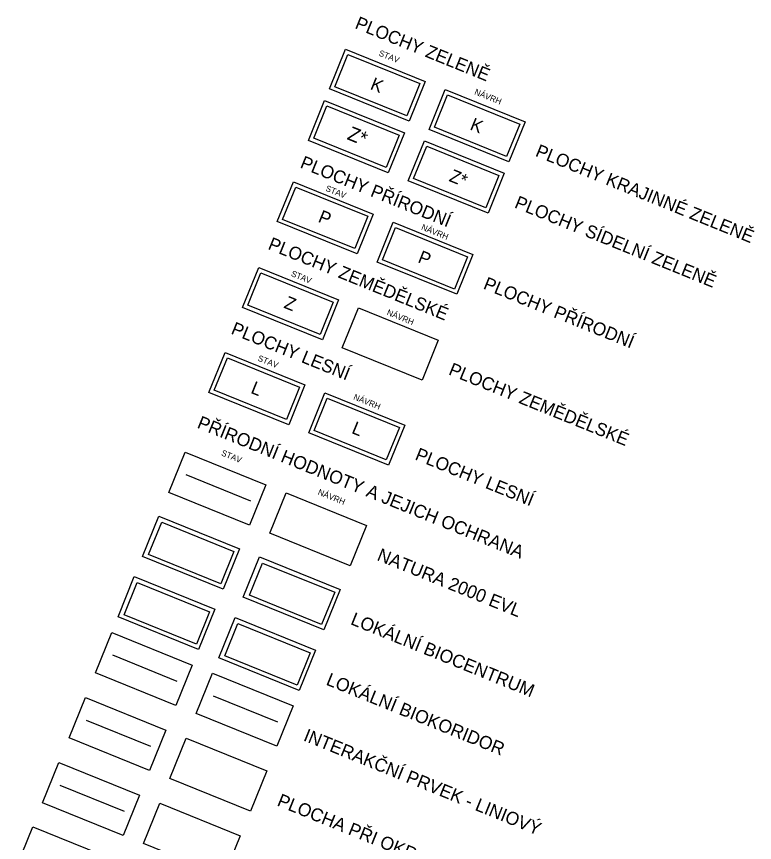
# Model space of a CAD drawing. Extents: x -522797 to -519326, y -1191143 to -1184078.
# Drawn here: x -522348 to -521499, y -1188829 to -1187879 of the extents above; entities that cross this region are included whole.
import ezdxf

# ---------------------------------------------------------------- set-up
doc = ezdxf.new("R2010")
doc.units = 0
for name, color, linetype in [('DOPRAVA', 7, 'Continuous'), ('Implicitní', 7, 'Continuous'), ('LBK_n', 7, 'Continuous'), ('LBK_s', 7, 'Continuous'), ('ložisk_nerost', 7, 'Continuous'), ('Natura2000_s', 7, 'Continuous'), ('OSTATNÍ', 7, 'Continuous')]:
    doc.layers.add(name, color=color, linetype=linetype)

msp = doc.modelspace()

# ---------------------------------------------------------------- linework, layer by layer
at = {"layer": 'DOPRAVA'}
for points in [[(-522153.6, -1188379.71), (-522060.92, -1188417.27), (-522079.7, -1188463.61), (-522172.38, -1188426.05)], [(-522037.75, -1188426.66), (-521945.07, -1188464.22), (-521963.85, -1188510.56), (-522056.53, -1188473)], [(-522268.5, -1188661.94), (-522175.82, -1188699.5), (-522194.6, -1188745.84), (-522287.28, -1188708.28)], [(-522152.65, -1188708.89), (-522059.97, -1188746.45), (-522078.75, -1188792.79), (-522171.43, -1188755.23)], [(-522298.8, -1188736.72), (-522206.12, -1188774.28), (-522224.9, -1188820.62), (-522317.58, -1188783.06)], [(-522182.95, -1188783.67), (-522090.28, -1188821.23), (-522109.06, -1188867.57), (-522201.73, -1188830.01)]]:
    msp.add_lwpolyline(points, close=True, dxfattribs=at)
at = {"layer": 'Implicitní'}
for p, q in [((-522237.37, -1188613.07), (-522163.23, -1188643.12)), ((-522121.52, -1188660.02), (-522047.38, -1188690.07))]:
    msp.add_line(p, q, dxfattribs=at)
for points in [[(-521969.3, -1187916.27), (-521877.54, -1187953.43), (-521896.12, -1187999.31), (-521987.88, -1187962.15)], [(-521966.71, -1187922.39), (-521883.67, -1187956.03), (-521898.72, -1187993.19), (-521981.76, -1187959.55)], [(-521854.6, -1187962.72), (-521762.84, -1187999.89), (-521781.42, -1188045.77), (-521873.18, -1188008.6)], [(-521852.01, -1187968.85), (-521768.97, -1188002.48), (-521784.02, -1188039.65), (-521867.06, -1188006.01)], [(-521993.29, -1187975.5), (-521901.53, -1188012.67), (-521920.11, -1188058.55), (-522011.87, -1188021.38)], [(-521990.7, -1187981.62), (-521907.65, -1188015.26), (-521922.71, -1188052.42), (-522005.75, -1188018.79)], [(-521878.59, -1188021.96), (-521786.83, -1188059.12), (-521805.41, -1188105), (-521897.17, -1188067.84)], [(-521875.98, -1188028.04), (-521792.94, -1188061.67), (-521807.99, -1188098.83), (-521891.03, -1188065.2)], [(-522029.2, -1188068.83), (-521937.44, -1188105.99), (-521956.02, -1188151.87), (-522047.78, -1188114.71)], [(-522026.61, -1188074.95), (-521943.56, -1188108.59), (-521958.62, -1188145.75), (-522041.66, -1188112.11)], [(-521914.5, -1188115.29), (-521822.74, -1188152.45), (-521841.32, -1188198.33), (-521933.08, -1188161.16)], [(-521911.91, -1188121.41), (-521828.86, -1188155.04), (-521843.92, -1188192.21), (-521926.96, -1188158.57)], [(-522069.11, -1188167.46), (-521977.35, -1188204.63), (-521995.94, -1188250.51), (-522087.69, -1188213.34)], [(-522066.52, -1188173.59), (-521983.48, -1188207.22), (-521998.53, -1188244.38), (-522081.57, -1188210.75)], [(-521954.41, -1188213.92), (-521862.65, -1188251.09), (-521881.24, -1188296.97), (-521973, -1188259.8)], [(-522107.72, -1188265.24), (-522015.96, -1188302.41), (-522034.54, -1188348.29), (-522126.3, -1188311.12)], [(-522105.12, -1188271.37), (-522022.08, -1188305), (-522037.13, -1188342.17), (-522120.17, -1188308.53)], [(-521993.02, -1188311.7), (-521901.26, -1188348.87), (-521919.84, -1188394.75), (-522011.6, -1188357.58)], [(-521990.42, -1188317.82), (-521907.38, -1188351.46), (-521922.43, -1188388.62), (-522005.47, -1188354.99)], [(-522183.99, -1188453.44), (-522091.32, -1188491), (-522110.1, -1188537.34), (-522202.77, -1188499.78)], [(-522180.65, -1188460.37), (-522097.61, -1188494.01), (-522112.67, -1188531.17), (-522195.71, -1188497.53)], [(-522068.15, -1188500.39), (-521975.47, -1188537.95), (-521994.25, -1188584.29), (-522086.93, -1188546.73)], [(-522064.81, -1188507.32), (-521981.77, -1188540.96), (-521996.82, -1188578.12), (-522079.86, -1188544.48)], [(-522212.16, -1188522.95), (-522119.49, -1188560.51), (-522138.27, -1188606.85), (-522230.94, -1188569.29)], [(-522096.32, -1188569.9), (-522003.64, -1188607.46), (-522022.42, -1188653.8), (-522115.1, -1188616.24)], [(-522238.19, -1188587.17), (-522145.51, -1188624.73), (-522164.29, -1188671.07), (-522256.97, -1188633.51)], [(-522122.34, -1188634.12), (-522029.67, -1188671.68), (-522048.45, -1188718.02), (-522141.12, -1188680.46)], [(-522328.86, -1188810.87), (-522236.18, -1188848.43), (-522254.96, -1188894.77), (-522347.64, -1188857.21)]]:
    msp.add_lwpolyline(points, close=True, dxfattribs=at)
at = {"layer": 'LBK_n'}
msp.add_lwpolyline([(-522092.98, -1188576.83), (-522009.94, -1188610.47), (-522024.99, -1188647.63), (-522108.03, -1188613.99)], close=True, dxfattribs=at)
at = {"layer": 'LBK_s'}
msp.add_lwpolyline([(-522208.82, -1188529.87), (-522125.79, -1188563.52), (-522140.84, -1188600.68), (-522223.88, -1188567.04)], close=True, dxfattribs=at)
at = {"layer": 'ložisk_nerost'}
msp.add_line((-522297.98, -1188762.62), (-522223.84, -1188792.67), dxfattribs=at)
at = {"layer": 'Natura2000_s'}
msp.add_line((-522152.78, -1188405.61), (-522078.64, -1188435.66), dxfattribs=at)
at = {"layer": 'OSTATNÍ'}
msp.add_line((-522267.67, -1188687.85), (-522193.53, -1188717.9), dxfattribs=at)

# ---------------------------------------------------------------- texts
at = {"layer": 'DOPRAVA'}
for s, p in [('PŘÍRODNÍ HODNOTY A JEJICH OCHRANA', (-522140.96, -1188351.48)), ('NATURA 2000 EVL', (-521934.11, -1188503.73)), ('PLOCHA PŘI OKRAJI LESA S PODM. VYUŽITÍM', (-522049.01, -1188785.96))]:
    msp.add_text(s, height=15, rotation=337.93806, dxfattribs=at).set_placement(p)
at = {"layer": 'Implicitní'}
for s, height, rotation, p in [('PLOCHY ZELENĚ', 14.85, 337.95056, (-521959.47, -1187892)), ('STAV', 6.93, 337.95056, (-521931.71, -1187923.54)), ('K', 14.85, 337.95056, (-521941.91, -1187962.07)), ('NÁVRH', 6.93, 337.95056, (-521821.67, -1187968.11)), ('K', 14.85, 337.95056, (-521827.22, -1188008.53)), ('Z*', 16.335, 337.95056, (-521968.47, -1188019.74)), ('PLOCHY KRAJINNÉ ZELENĚ', 14.85, 337.95056, (-521751.98, -1188039)), ('PLOCHY PŘÍRODNÍ', 14.85, 337.95056, (-522022.52, -1188052.33)), ('Z*', 14.85, 337.95056, (-521851.24, -1188067.75)), ('STAV', 6.93, 337.95056, (-521992.83, -1188079.1)), ('PLOCHY SÍDELNÍ ZELENĚ', 14.85, 337.95056, (-521775.97, -1188098.24)), ('P', 14.85, 337.95056, (-522001.81, -1188114.63)), ('NÁVRH', 6.93, 337.95056, (-521882.78, -1188123.67)), ('PLOCHY ZEMĚDĚLSKÉ', 14.85, 337.95056, (-522059.46, -1188145.92)), ('P', 14.85, 337.95056, (-521887.11, -1188161.09)), ('STAV', 6.93, 337.95056, (-522032.5, -1188177.14)), ('PLOCHY PŘÍRODNÍ', 14.85, 337.95056, (-521811.88, -1188191.56)), ('Z', 14.85, 337.95056, (-522041.19, -1188213.49)), ('NÁVRH', 6.93, 337.95056, (-521922.45, -1188221.71)), ('PLOCHY LESNÍ', 14.85, 337.95056, (-522101.95, -1188243.33)), ('STAV', 6.93, 337.95056, (-522070.87, -1188274.36)), ('PLOCHY ZEMĚDĚLSKÉ', 14.85, 337.95056, (-521851.79, -1188290.2)), ('L', 14.85, 337.95056, (-522079.26, -1188311.48)), ('NÁVRH', 6.93, 337.95056, (-521960.83, -1188318.94)), ('L', 14.85, 337.95056, (-521963.25, -1188357.69)), ('STAV', 7, 337.93806, (-522112.93, -1188383.34)), ('PLOCHY LESNÍ', 14.85, 337.95056, (-521890.4, -1188387.98)), ('NÁVRH', 7, 337.93806, (-522001.78, -1188428.39)), ('LOKÁLNÍ BIOCENTRUM ', 15, 337.93806, (-521964.51, -1188577.46)), ('LOKÁLNÍ BIOKORIDOR', 15, 337.93806, (-521992.68, -1188646.97)), ('INTERAKČNÍ PRVEK - LINIOVÝ', 15, 337.93806, (-522018.7, -1188711.19))]:
    msp.add_text(s, height=height, rotation=rotation, dxfattribs=at).set_placement(p)

doc.saveas('drawing.dxf')
